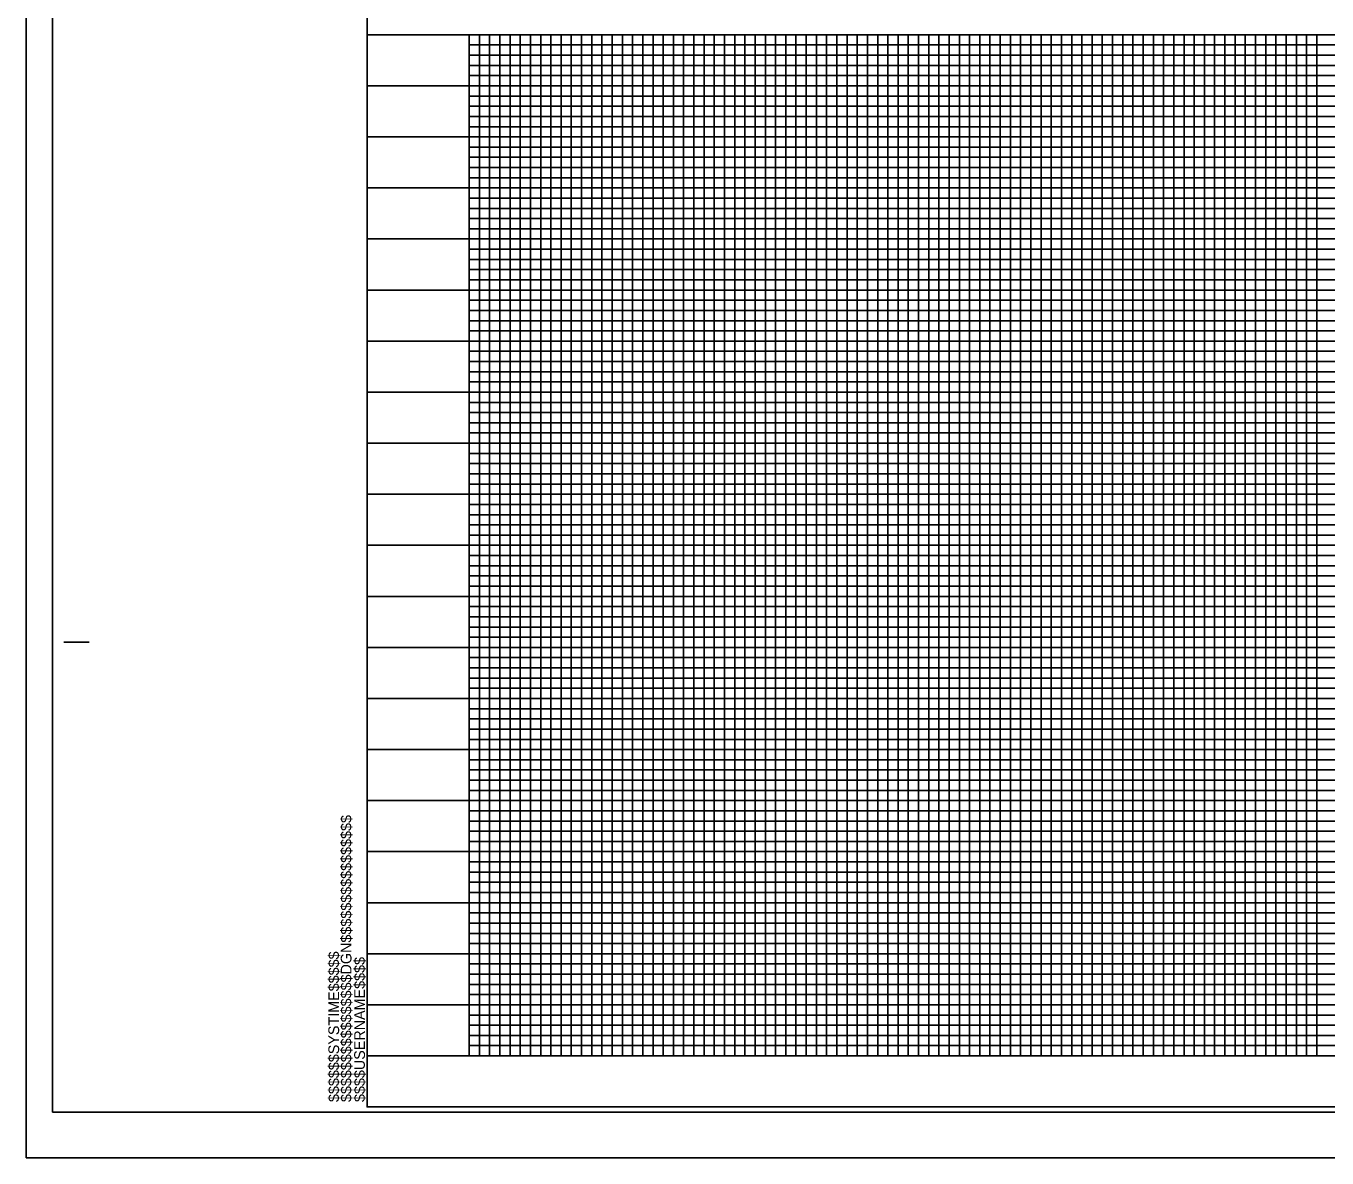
# Model space of a CAD drawing. Extents: x 1810963 to 1812934, y 722070 to 723170.
# Drawn here: x 1810963 to 1811600, y 722070 to 722624 of the extents above; entities that cross this region are included whole.
import ezdxf

# ---------------------------------------------------------------- set-up
doc = ezdxf.new("R2010")
doc.units = 0
for name, color, linetype in [('Old_Level_11', 7, 'Continuous'), ('Prop Conc 2ft 6in Curb and Gutter', 7, 'Continuous'), ('Prop PFL VPI Symbol CELL', 7, 'Continuous'), ('Prop RDY Traffic Signal CELL', 7, 'Continuous'), ('Prop Shade Heavy', 7, 'Continuous'), ('Prop Shade Light', 7, 'Continuous'), ('Sheet North Arrow CELL', 7, 'Continuous'), ('Sheet Symbology CELL', 7, 'Continuous'), ('Sheet Title CELL', 7, 'Continuous')]:
    doc.layers.add(name, color=color, linetype=linetype)

msp = doc.modelspace()

# ---------------------------------------------------------------- linework, layer by layer
at = {"layer": 'Old_Level_11'}
msp.add_lwpolyline([(1810976.46, 722092.33), (1812642.96, 722092.33), (1812642.96, 723147.43), (1810976.46, 723147.43)], close=True, dxfattribs=at)
at = {"layer": 'Prop Conc 2ft 6in Curb and Gutter'}
for p, q in [((1811130.46, 722619.88), (1812630.35, 722619.88)), ((1811180.46, 722619.88), (1811180.46, 722119.88)), ((1811230.46, 722619.88), (1811230.46, 722119.88)), ((1811280.46, 722619.88), (1811280.46, 722119.88)), ((1811330.46, 722619.88), (1811330.46, 722119.88)), ((1811380.46, 722619.88), (1811380.46, 722119.88)), ((1811430.46, 722619.88), (1811430.46, 722119.88)), ((1811480.46, 722619.88), (1811480.46, 722119.88)), ((1811530.46, 722619.88), (1811530.46, 722119.88)), ((1811580.46, 722619.88), (1811580.46, 722119.88)), ((1811130.46, 722569.88), (1812630.35, 722569.88)), ((1811130.46, 722519.88), (1812630.35, 722519.88)), ((1811130.46, 722469.88), (1812630.35, 722469.88)), ((1811130.46, 722419.88), (1812630.35, 722419.88)), ((1811130.46, 722369.88), (1812630.35, 722369.88)), ((1811130.46, 722319.88), (1812630.35, 722319.88)), ((1811130.46, 722269.88), (1812630.35, 722269.88)), ((1811130.46, 722219.88), (1812630.35, 722219.88)), ((1811130.46, 722169.88), (1812630.35, 722169.88))]:
    msp.add_line(p, q, dxfattribs=at)
at = {"layer": 'Prop PFL VPI Symbol CELL'}
msp.add_lwpolyline([(1811180.46, 722619.88), (1812580.46, 722619.88), (1812580.46, 722119.88), (1811180.46, 722119.88)], close=True, dxfattribs=at)
at = {"layer": 'Prop RDY Traffic Signal CELL'}
for p, q in [((1810963.46, 723169.88), (1810963.46, 722069.88)), ((1810963.46, 722069.88), (1812647.46, 722069.88))]:
    msp.add_line(p, q, dxfattribs=at)
at = {"layer": 'Prop Shade Heavy'}
msp.add_line((1811130.46, 722119.88), (1811130.46, 722119.88), dxfattribs=at)
for points in [[(1811180.46, 722619.88), (1811180.46, 722119.88), (1811230.46, 722119.88), (1811230.46, 722619.88), (1811280.46, 722619.88), (1811280.46, 722119.88), (1811330.46, 722119.88), (1811330.46, 722619.88), (1811380.46, 722619.88), (1811380.46, 722119.88), (1811430.46, 722119.88), (1811430.46, 722619.88), (1811480.46, 722619.88), (1811480.46, 722119.88), (1811530.46, 722119.88), (1811530.46, 722619.88), (1811580.46, 722619.88), (1811580.46, 722119.88), (1811630.46, 722119.88)], [(1812630.46, 722569.88), (1811130.46, 722569.88)], [(1812630.46, 722519.88), (1811130.46, 722519.88), (1811130.46, 722469.88), (1812630.46, 722469.88)], [(1812630.46, 722419.88), (1811130.46, 722419.88), (1811130.46, 722369.88), (1812630.46, 722369.88)], [(1812630.46, 722319.88), (1811130.46, 722319.88), (1811130.46, 722269.88), (1812630.46, 722269.88)], [(1812630.46, 722219.88), (1811130.46, 722219.88), (1811130.46, 722219.88), (1811130.46, 722169.88), (1812630.46, 722169.88)], [(1812630.46, 722119.88), (1811130.46, 722119.88)]]:
    msp.add_lwpolyline(points, dxfattribs=at)
at = {"layer": 'Prop Shade Light'}
for points in [[(1811155.46, 722619.88), (1811205.46, 722619.88), (1811205.46, 722119.88), (1811255.46, 722119.88), (1811255.46, 722619.88), (1811305.46, 722619.88), (1811305.46, 722119.88), (1811355.46, 722119.88), (1811355.46, 722619.88), (1811405.46, 722619.88), (1811405.46, 722119.88), (1811455.46, 722119.88), (1811455.46, 722619.88), (1811505.46, 722619.88), (1811505.46, 722119.88), (1811555.46, 722119.88), (1811555.46, 722619.88), (1811605.46, 722619.88)], [(1811130.46, 722594.88), (1812630.46, 722594.88)], [(1812630.46, 722544.88), (1811130.46, 722544.88), (1811130.46, 722494.88), (1812630.46, 722494.88)], [(1812630.46, 722444.88), (1811130.46, 722444.88), (1811130.46, 722394.88), (1812630.46, 722394.88)], [(1812630.46, 722344.88), (1811130.46, 722344.88), (1811130.46, 722294.88), (1812630.46, 722294.88)], [(1812630.46, 722244.88), (1811130.46, 722244.88), (1811130.46, 722194.88), (1812630.46, 722194.88)], [(1812630.46, 722144.88), (1811130.46, 722144.88)]]:
    msp.add_lwpolyline(points, dxfattribs=at)
at = {"layer": 'Sheet North Arrow CELL'}
msp.add_lwpolyline([(1810963.46, 722069.88), (1812647.46, 722069.88), (1812647.46, 723169.88), (1810963.46, 723169.88)], close=True, dxfattribs=at)
at = {"layer": 'Sheet Symbology CELL'}
for p, q in [((1811130.46, 722619.88), (1812630.46, 722619.88)), ((1810981.96, 722322.38), (1810994.46, 722322.38)), ((1812630.46, 722119.88), (1811130.46, 722119.88)), ((1811130.46, 722094.88), (1812630.46, 722094.88)), ((1811130.46, 722094.88), (1811130.46, 722094.88)), ((1811130.46, 722094.88), (1811130.46, 722094.88)), ((1811130.46, 722094.88), (1811130.46, 722094.88)), ((1811130.46, 722094.88), (1811130.46, 722094.88)), ((1811130.46, 722094.88), (1811130.46, 722094.88)), ((1811130.46, 722094.88), (1811130.46, 722094.88)), ((1811130.46, 722094.88), (1811130.46, 722094.88))]:
    msp.add_line(p, q, dxfattribs=at)
msp.add_lwpolyline([(1812630.46, 723144.88), (1811130.46, 723144.88), (1811130.46, 722094.88), (1812630.46, 722094.88)], close=True, dxfattribs=at)
msp.add_lwpolyline([(1811160.99, 722094.88), (1811160.99, 722094.88)], dxfattribs=at)
at = {"layer": 'Sheet Title CELL'}
for p, q in [((1811180.46, 722614.88), (1812580.46, 722614.88)), ((1812580.46, 722609.88), (1811180.46, 722609.88)), ((1811180.46, 722604.88), (1812580.46, 722604.88)), ((1812580.46, 722599.88), (1811180.46, 722599.88)), ((1811180.46, 722589.88), (1812580.46, 722589.88)), ((1812580.46, 722584.88), (1811180.46, 722584.88)), ((1811180.46, 722579.88), (1812580.46, 722579.88)), ((1812580.46, 722574.88), (1811180.46, 722574.88)), ((1811180.46, 722564.88), (1812580.46, 722564.88)), ((1812580.46, 722559.88), (1811180.46, 722559.88)), ((1811180.46, 722554.88), (1812580.46, 722554.88)), ((1812580.46, 722549.88), (1811180.46, 722549.88)), ((1811180.46, 722539.88), (1812580.46, 722539.88)), ((1812580.46, 722534.88), (1811180.46, 722534.88)), ((1811180.46, 722529.88), (1812580.46, 722529.88)), ((1812580.46, 722524.88), (1811180.46, 722524.88)), ((1811180.46, 722514.88), (1812580.46, 722514.88)), ((1812580.46, 722509.88), (1811180.46, 722509.88)), ((1811180.46, 722504.88), (1812580.46, 722504.88)), ((1812580.46, 722499.88), (1811180.46, 722499.88)), ((1811180.46, 722489.88), (1812580.46, 722489.88)), ((1812580.46, 722484.88), (1811180.46, 722484.88)), ((1811180.46, 722479.88), (1812580.46, 722479.88)), ((1812580.46, 722474.88), (1811180.46, 722474.88)), ((1811180.46, 722464.88), (1812580.46, 722464.88)), ((1812580.46, 722459.88), (1811180.46, 722459.88)), ((1811180.46, 722454.88), (1812580.46, 722454.88)), ((1812580.46, 722449.88), (1811180.46, 722449.88)), ((1811180.46, 722439.88), (1812580.46, 722439.88)), ((1812580.46, 722434.88), (1811180.46, 722434.88)), ((1811180.46, 722429.88), (1812580.46, 722429.88)), ((1812580.46, 722424.88), (1811180.46, 722425.03)), ((1811180.46, 722414.88), (1812580.46, 722414.88)), ((1812580.46, 722409.88), (1811180.46, 722409.88)), ((1811180.46, 722404.88), (1812580.46, 722404.88)), ((1812580.46, 722399.88), (1811180.46, 722399.88)), ((1811180.46, 722389.88), (1812580.46, 722389.88)), ((1812580.46, 722384.88), (1811180.46, 722384.88)), ((1811180.46, 722379.88), (1812580.46, 722379.88)), ((1812580.46, 722374.88), (1811180.46, 722374.88)), ((1811180.46, 722364.88), (1812580.46, 722364.88)), ((1812580.46, 722359.88), (1811180.46, 722359.88)), ((1811180.46, 722354.88), (1812580.46, 722354.88)), ((1812580.46, 722349.88), (1811180.46, 722349.88)), ((1811180.46, 722339.88), (1812580.46, 722339.88)), ((1812580.46, 722334.88), (1811180.46, 722334.88)), ((1811180.46, 722329.88), (1812580.46, 722329.88)), ((1812580.46, 722324.88), (1811180.46, 722324.88)), ((1811180.46, 722314.88), (1812580.46, 722314.88)), ((1812580.46, 722309.88), (1811180.46, 722309.88)), ((1811180.46, 722304.88), (1812580.46, 722304.88)), ((1812580.46, 722299.88), (1811180.46, 722299.88)), ((1811180.46, 722289.88), (1812580.46, 722289.88)), ((1812580.46, 722284.88), (1811180.46, 722284.88)), ((1811180.46, 722279.88), (1812580.46, 722279.88)), ((1812580.46, 722274.88), (1811180.46, 722274.88)), ((1811180.46, 722264.88), (1812580.46, 722264.88)), ((1812580.46, 722259.88), (1811180.46, 722259.88)), ((1811180.46, 722254.88), (1812580.46, 722254.88)), ((1812580.46, 722249.88), (1811180.46, 722249.88)), ((1811180.46, 722239.88), (1812580.46, 722239.88)), ((1812580.46, 722234.88), (1811180.46, 722234.88)), ((1811180.46, 722229.88), (1812580.46, 722229.88)), ((1812580.46, 722224.88), (1811180.46, 722224.88)), ((1811180.46, 722214.88), (1812580.46, 722214.88)), ((1812580.46, 722209.88), (1811180.46, 722209.88)), ((1811180.46, 722204.88), (1812580.46, 722204.88)), ((1812580.46, 722199.88), (1811180.46, 722199.88)), ((1811180.46, 722189.88), (1812580.46, 722189.88)), ((1812580.46, 722184.88), (1811180.46, 722184.88)), ((1811180.46, 722179.88), (1812580.46, 722179.88)), ((1812580.46, 722174.88), (1811180.46, 722174.88)), ((1811180.46, 722164.88), (1812580.46, 722164.88)), ((1812580.46, 722159.88), (1811180.46, 722159.88)), ((1811180.46, 722154.88), (1812580.46, 722154.88)), ((1812580.46, 722149.88), (1811180.46, 722149.88)), ((1811180.46, 722139.88), (1812580.46, 722139.88)), ((1812580.46, 722134.88), (1811180.46, 722134.88)), ((1811180.46, 722129.88), (1812580.46, 722129.88)), ((1811180.46, 722124.88), (1812580.46, 722124.88))]:
    msp.add_line(p, q, dxfattribs=at)
for points in [[(1811180.46, 722619.88), (1811185.46, 722619.88), (1811185.46, 722119.88), (1811190.46, 722119.88), (1811190.46, 722619.88), (1811195.46, 722619.88), (1811195.46, 722119.88), (1811200.46, 722119.88), (1811200.46, 722619.88), (1811210.46, 722619.88), (1811210.46, 722119.88), (1811215.46, 722119.88), (1811215.46, 722619.88), (1811220.46, 722619.88), (1811220.46, 722119.88), (1811225.46, 722119.88), (1811235.46, 722119.88), (1811240.46, 722119.88), (1811240.46, 722619.88), (1811245.46, 722619.88), (1811245.46, 722119.88), (1811250.46, 722119.88), (1811250.46, 722619.88), (1811260.46, 722619.88), (1811260.46, 722119.88), (1811265.46, 722119.88), (1811265.46, 722619.88), (1811270.46, 722619.88), (1811270.46, 722119.88), (1811275.46, 722119.88), (1811275.46, 722619.88), (1811285.46, 722619.88), (1811285.46, 722119.88), (1811290.46, 722119.88), (1811290.46, 722619.88), (1811295.46, 722619.88), (1811295.46, 722119.88), (1811300.46, 722119.88), (1811300.46, 722619.88), (1811310.46, 722619.88), (1811310.46, 722119.88), (1811315.46, 722119.88), (1811315.46, 722619.88), (1811320.46, 722619.88), (1811320.46, 722119.88), (1811325.46, 722119.88), (1811325.46, 722619.88), (1811335.46, 722619.88), (1811335.46, 722119.88), (1811340.46, 722119.88), (1811340.46, 722619.88), (1811345.46, 722619.88), (1811345.46, 722119.88), (1811350.46, 722119.88), (1811350.46, 722619.88), (1811360.46, 722619.88), (1811360.46, 722119.88), (1811365.46, 722119.88), (1811365.46, 722619.88), (1811370.46, 722619.88), (1811370.46, 722119.88), (1811375.46, 722119.88), (1811375.46, 722619.88), (1811385.46, 722619.88), (1811385.46, 722119.88), (1811390.46, 722119.88), (1811390.46, 722619.88), (1811395.46, 722619.88), (1811395.46, 722119.88)], [(1811225.46, 722119.88), (1811225.46, 722619.88), (1811235.46, 722619.88), (1811235.46, 722119.88)], [(1811395.46, 722119.88), (1811400.46, 722119.88), (1811400.46, 722619.88), (1811410.46, 722619.88), (1811410.46, 722119.88), (1811415.46, 722119.88), (1811415.46, 722619.88), (1811420.46, 722619.88), (1811420.46, 722119.88), (1811425.46, 722119.88), (1811425.46, 722619.88), (1811435.46, 722619.88), (1811435.46, 722119.88), (1811440.46, 722119.88), (1811440.46, 722619.88), (1811445.46, 722619.88), (1811445.46, 722119.88), (1811450.46, 722119.88), (1811450.46, 722619.88), (1811460.46, 722619.88), (1811460.46, 722119.88), (1811465.46, 722119.88), (1811465.46, 722619.88), (1811470.46, 722619.88), (1811470.46, 722119.88), (1811475.46, 722119.88), (1811475.46, 722619.88), (1811485.46, 722619.88), (1811485.46, 722119.88), (1811490.46, 722119.88), (1811490.46, 722619.88), (1811495.46, 722619.88), (1811495.46, 722119.88), (1811500.46, 722119.88), (1811500.46, 722619.88), (1811510.46, 722619.88), (1811510.46, 722119.88), (1811515.46, 722119.88), (1811515.46, 722619.88), (1811520.46, 722619.88), (1811520.46, 722119.88), (1811525.46, 722119.88), (1811525.46, 722619.88), (1811535.46, 722619.88), (1811535.46, 722119.88), (1811540.46, 722119.88), (1811540.46, 722619.88), (1811545.46, 722619.88), (1811545.46, 722119.88), (1811550.46, 722119.88), (1811550.46, 722619.88), (1811560.46, 722619.88), (1811560.46, 722119.88), (1811565.46, 722119.88), (1811565.46, 722619.88), (1811570.46, 722619.88), (1811570.46, 722119.88), (1811575.46, 722119.88), (1811575.46, 722619.88), (1811585.46, 722619.88), (1811585.46, 722119.88), (1811590.46, 722119.88), (1811590.46, 722619.88), (1811595.46, 722619.88), (1811595.46, 722119.88), (1811600.46, 722119.88)]]:
    msp.add_lwpolyline(points, dxfattribs=at)

# ---------------------------------------------------------------- texts
at = {"layer": 'Sheet Symbology CELL'}
for s, p in [('$$$$$$$$$$$$$$$$DGN$$$$$$$$$$$$$$$$', (1811122.82, 722097.26)), ('$$$$$$SYSTIME$$$$$', (1811116.77, 722097.26)), ('$$$$USERNAME$$$$', (1811129.4, 722097.27))]:
    msp.add_text(s, height=5.25, rotation=90, dxfattribs=at).set_placement(p)

doc.saveas('drawing.dxf')
